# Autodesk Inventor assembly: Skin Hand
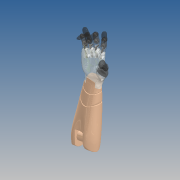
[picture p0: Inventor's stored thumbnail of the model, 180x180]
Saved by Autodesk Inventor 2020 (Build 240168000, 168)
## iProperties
Created: 2019-10
Part Number: Skin Hand
Document SubType Name: Assembly
Designer: yello
Author: yello
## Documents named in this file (21)
- C:\Users\yello\Documents\Mechanical Hand\Prototype 2 (Realistic Hand)\Skin Hand.iam
- C:\Users\yello\Documents\Mechanical Hand\Prototype 2 (Realistic Hand)\Palm.ipt
- C:\Users\yello\Documents\Mechanical Hand\Prototype 2 (Realistic Hand)\Wrist Rotation.ipt
- C:\Users\yello\Documents\Mechanical Hand\Prototype 2 (Realistic Hand)\Arm to Wrist Connection.ipt
- C:\Users\yello\Documents\Mechanical Hand\Prototype 2 (Realistic Hand)\Arm.ipt
- C:\Users\yello\Documents\Mechanical Hand\Prototype 2 (Realistic Hand)\Segment Thumb Finger Bottom.ipt
- C:\Users\yello\Documents\Mechanical Hand\Prototype 2 (Realistic Hand)\Segment Thumb Finger Middle.ipt
- C:\Users\yello\Documents\Mechanical Hand\Prototype 2 (Realistic Hand)\Segment Thumb Finger Top.ipt
- C:\Users\yello\Documents\Mechanical Hand\Prototype 2 (Realistic Hand)\Segment Index Finger Middle.ipt
- C:\Users\yello\Documents\Mechanical Hand\Prototype 2 (Realistic Hand)\Segment Index Finger Top.ipt
- C:\Users\yello\Documents\Mechanical Hand\Prototype 2 (Realistic Hand)\Segment Middle Finger Middle.ipt
- C:\Users\yello\Documents\Mechanical Hand\Prototype 2 (Realistic Hand)\Segment Middle Finger Top.ipt
- C:\Users\yello\Documents\Mechanical Hand\Prototype 2 (Realistic Hand)\Segment Ring Finger Middle.ipt
- C:\Users\yello\Documents\Mechanical Hand\Prototype 2 (Realistic Hand)\Segment Ring Finger Top.ipt
- C:\Users\yello\Documents\Mechanical Hand\Prototype 2 (Realistic Hand)\Segment Pinkie Finger Middle.ipt
- C:\Users\yello\Documents\Mechanical Hand\Prototype 2 (Realistic Hand)\Segment Pinkie Finger Top.ipt
- C:\Users\yello\Documents\Mechanical Hand\Prototype 2 (Realistic Hand)\Segment Index Finger Bottom Ball.iam
- C:\Users\yello\Documents\Mechanical Hand\Prototype 2 (Realistic Hand)\Segment Middle Finger Bottom Ball.iam
- C:\Users\yello\Documents\Mechanical Hand\Prototype 2 (Realistic Hand)\Segment Ring Finger Bottom Ball.iam
- C:\Users\yello\Documents\Mechanical Hand\Prototype 2 (Realistic Hand)\Segment Pinkie Finger Bottom Ball.iam
- C:\Users\yello\Documents\Mechanical Hand\Prototype 2 (Realistic Hand)\Bearings.iam
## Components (23 placed, 20 different names)
1. Palm:1 — Rotational:1, Rotational:2, Rotational:17, Rotational:18, Rotational:19, Rotational:20
2. Wrist Rotation:1 — Rotational:1, Mate:1, Mate:2, Mate:4
3. Arm to Wrist Connection:1 — Mate:1, Mate:2, Mate:3
4. Arm:1 — Mate:3, Mate:4
5. Segment Thumb Finger Bottom:1 — Rotational:2, Rotational:3
6. Segment Thumb Finger Middle:1 — Rotational:3, Rotational:4
7. Segment Thumb Finger Top:1 — Rotational:4
8. Segment Index Finger Middle:1 — Rotational:24, Rotational:25, Mate:5, Flush:1
9. Segment Index Finger Top:1 — Rotational:25
10. Segment Middle Finger Middle:1 — Rotational:10, Rotational:23, Mate:6, Flush:2
11. Segment Middle Finger Top:1 — Rotational:10
12. Segment Ring Finger Middle:1 — Rotational:13, Rotational:22, Mate:7, Flush:3
13. Segment Ring Finger Top:1 — Rotational:13
14. Segment Pinkie Finger Middle:1 — Rotational:16, Rotational:21, Mate:8, Flush:4
15. Segment Pinkie Finger Top:1 — Rotational:16
16. Segment Index Finger Bottom Ball:1 [sub-assembly] — Rotational:17, Rotational:24
17. Segment Middle Finger Bottom Ball:1 [sub-assembly] — Rotational:18, Rotational:23
18. Segment Ring Finger Bottom Ball:1 [sub-assembly] — Rotational:19, Rotational:22
19. Segment Pinkie Finger Bottom Ball:1 [sub-assembly] — Rotational:20, Rotational:21
20. Bearings:1 [sub-assembly] — Mate:5, Flush:1
21. Bearings:2 [sub-assembly] — Mate:6, Flush:2
22. Bearings:3 [sub-assembly] — Mate:7, Flush:3
23. Bearings:4 [sub-assembly] — Mate:8, Flush:4
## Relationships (28: RevoluteJoint 16, Mate 8, Flush 4)
- Rotational:1 [RevoluteJoint]: Palm:1 ↔ Wrist Rotation:1
- Mate:1: Wrist Rotation:1 ↔ Arm to Wrist Connection:1
- Mate:2: Wrist Rotation:1 ↔ Arm to Wrist Connection:1
- Mate:3: Arm to Wrist Connection:1 ↔ Arm:1
- Mate:4: Wrist Rotation:1 ↔ Arm:1
- Rotational:2 [RevoluteJoint]: Palm:1 ↔ Segment Thumb Finger Bottom:1
- Rotational:3 [RevoluteJoint]: Segment Thumb Finger Bottom:1 ↔ Segment Thumb Finger Middle:1
- Rotational:4 [RevoluteJoint]: Segment Thumb Finger Middle:1 ↔ Segment Thumb Finger Top:1
- Rotational:10 [RevoluteJoint]: Segment Middle Finger Middle:1 ↔ Segment Middle Finger Top:1
- Rotational:13 [RevoluteJoint]: Segment Ring Finger Middle:1 ↔ Segment Ring Finger Top:1
- Rotational:16 [RevoluteJoint]: Segment Pinkie Finger Middle:1 ↔ Segment Pinkie Finger Top:1
- Rotational:17 [RevoluteJoint]: Palm:1 ↔ Segment Index Finger Bottom Ball:1
- Rotational:18 [RevoluteJoint]: Palm:1 ↔ Segment Middle Finger Bottom Ball:1
- Rotational:19 [RevoluteJoint]: Palm:1 ↔ Segment Ring Finger Bottom Ball:1
- Rotational:20 [RevoluteJoint]: Palm:1 ↔ Segment Pinkie Finger Bottom Ball:1
- Rotational:21 [RevoluteJoint]: Segment Pinkie Finger Middle:1 ↔ Segment Pinkie Finger Bottom Ball:1
- Rotational:22 [RevoluteJoint]: Segment Ring Finger Middle:1 ↔ Segment Ring Finger Bottom Ball:1
- Rotational:23 [RevoluteJoint]: Segment Middle Finger Middle:1 ↔ Segment Middle Finger Bottom Ball:1
- Rotational:24 [RevoluteJoint]: Segment Index Finger Middle:1 ↔ Segment Index Finger Bottom Ball:1
- Rotational:25 [RevoluteJoint]: Segment Index Finger Middle:1 ↔ Segment Index Finger Top:1
- Mate:5: Segment Index Finger Middle:1 ↔ Bearings:1
- Flush:1: Segment Index Finger Middle:1 ↔ Bearings:1
- Mate:6: Segment Middle Finger Middle:1 ↔ Bearings:2
- Flush:2: Segment Middle Finger Middle:1 ↔ Bearings:2
- Mate:7: Segment Ring Finger Middle:1 ↔ Bearings:3
- Flush:3: Segment Ring Finger Middle:1 ↔ Bearings:3
- Mate:8: Segment Pinkie Finger Middle:1 ↔ Bearings:4
- Flush:4: Segment Pinkie Finger Middle:1 ↔ Bearings:4
